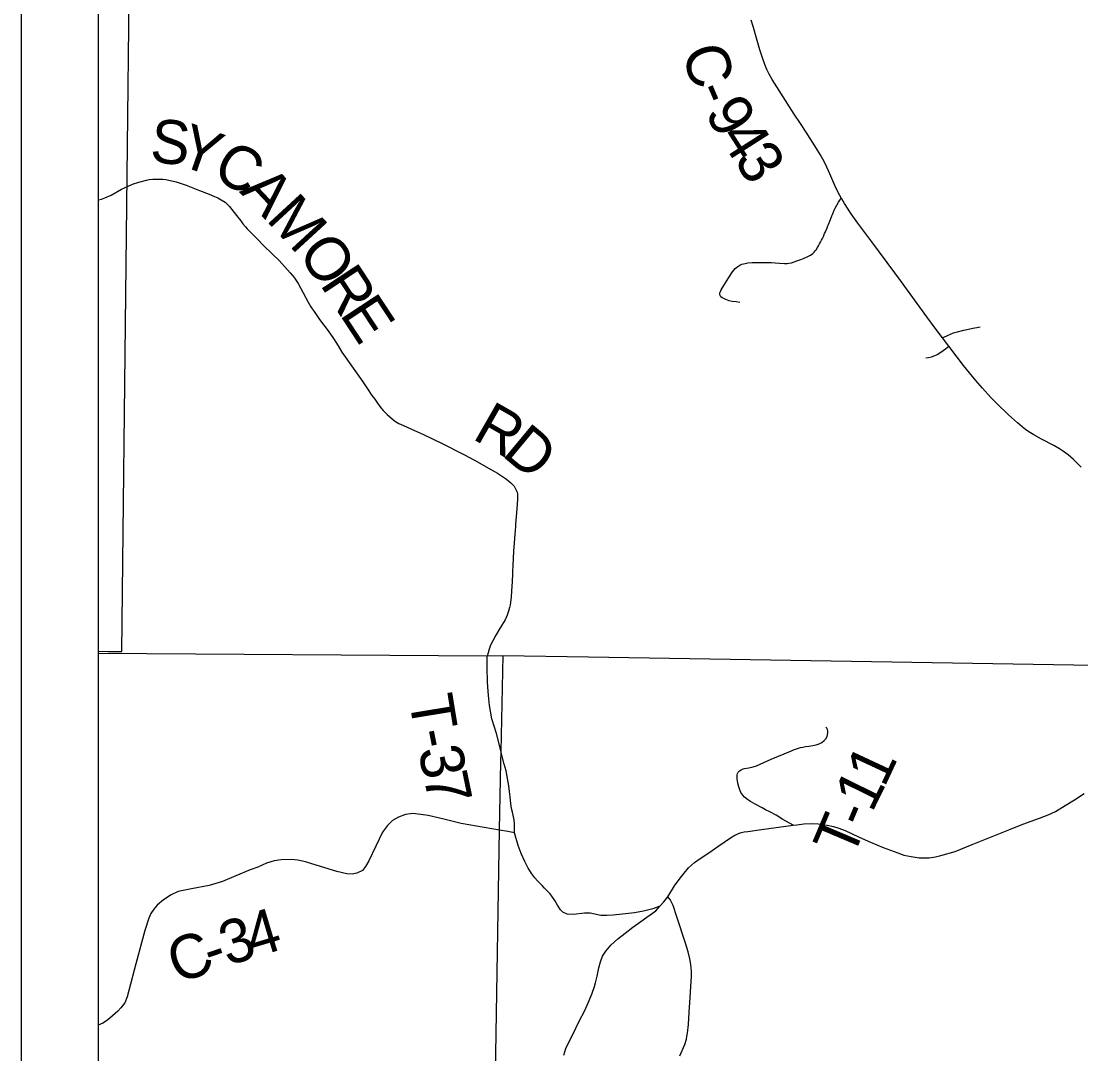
# Model space of a CAD drawing. Extents: x 0 to 34, y 0 to 22.
# Drawn here: x 2 to 3.375, y 18.658 to 19.997 of the extents above; entities that cross this region are included whole.
import ezdxf

# ---------------------------------------------------------------- set-up
doc = ezdxf.new("R2010")
doc.units = 0
for name, color, linetype in [('GM_X_Corporation', 7, 'Continuous'), ('GM_X_County_Road', 7, 'Continuous'), ('GM_X_County_Road_Text', 7, 'Continuous'), ('GM_X_Township_Road', 7, 'Continuous'), ('GM_X_Township_Road_Text', 7, 'Continuous'), ('GM_X_Township_Text', 7, 'Continuous'), ('SH_Data', 7, 'Continuous')]:
    doc.layers.add(name, color=color, linetype=linetype)

msp = doc.modelspace()

# ---------------------------------------------------------------- linework, layer by layer
at = {"layer": 'GM_X_Corporation'}
msp.add_lwpolyline([(2.1, 20.1831), (2.1, 19.1797), (2.1129, 19.1796), (2.1306, 19.1793), (2.142, 20.1827)], close=True, dxfattribs=at)
at = {"layer": 'GM_X_County_Road'}
msp.add_line((3.2036, 19.5753), (3.1953, 19.5861), dxfattribs=at)
for points in [[(3.0642, 19.767), (3.0601, 19.7746), (3.0555, 19.784), (3.049, 19.7988), (3.0433, 19.8113), (3.04, 19.818), (3.0366, 19.824), (3.0317, 19.8319), (3.0183, 19.8529), (3.0109, 19.8643), (3.003, 19.8762), (2.997, 19.8856), (2.9832, 19.9071), (2.9743, 19.9213), (2.9703, 19.9282), (2.9673, 19.9343), (2.9647, 19.9405), (2.9617, 19.9493), (2.9584, 19.9599), (2.954, 19.9749), (2.9499, 19.9886), (2.9469, 19.998)], [(3.1953, 19.5861), (3.1856, 19.5988), (3.1749, 19.6133), (3.1407, 19.6606), (3.1333, 19.6706), (3.1037, 19.7106), (3.0856, 19.7351), (3.0769, 19.7472), (3.068, 19.7606), (3.0645, 19.7664), (3.0642, 19.767)], [(3.3752, 19.4183), (3.3705, 19.4234), (3.3651, 19.4286), (3.3584, 19.4343), (3.3524, 19.4388), (3.3472, 19.4422), (3.3396, 19.4466), (3.3236, 19.455), (3.3138, 19.4603), (3.3075, 19.4642), (3.303, 19.4673), (3.2986, 19.4707), (3.2924, 19.4759), (3.281, 19.4864), (3.2662, 19.5006), (3.258, 19.509), (3.2471, 19.5209), (3.2383, 19.5312), (3.2226, 19.5505), (3.2143, 19.5613), (3.2036, 19.5753)], [(2.8388, 18.8614), (2.8475, 18.8754), (2.8548, 18.8856), (2.86, 18.8918), (2.8659, 18.899), (2.8735, 18.9057), (2.8808, 18.9111), (2.892, 18.9183), (2.9038, 18.9266), (2.9202, 18.9377), (2.9257, 18.9411), (2.9327, 18.9442), (2.938, 18.9456), (2.9426, 18.9462), (2.9603, 18.9487), (3.0016, 18.9541), (3.0061, 18.9546), (3.0153, 18.9558), (3.0248, 18.9563), (3.034, 18.956), (3.0456, 18.9542), (3.0539, 18.9525), (3.0608, 18.9502), (3.0691, 18.9472), (3.0771, 18.9433), (3.0872, 18.9387), (3.1017, 18.9322), (3.1181, 18.9253), (3.1372, 18.9182), (3.1453, 18.9155), (3.1545, 18.9135), (3.1648, 18.912), (3.1782, 18.9119), (3.1861, 18.913), (3.1933, 18.9147), (3.2118, 18.9202), (3.2339, 18.929), (3.2813, 18.9483), (3.2993, 18.9556), (3.321, 18.9632), (3.3325, 18.9677), (3.3417, 18.972), (3.3546, 18.9798), (3.3667, 18.9873), (3.3792, 18.9952)], [(2.6204, 18.9476), (2.5709, 18.9562), (2.5484, 18.9622), (2.5282, 18.9669), (2.5187, 18.9682), (2.5082, 18.9694), (2.4984, 18.9679), (2.4897, 18.9647), (2.4818, 18.9604), (2.4751, 18.9539), (2.4687, 18.9451), (2.4601, 18.9272), (2.4512, 18.9081), (2.4466, 18.9006), (2.4426, 18.8956), (2.4354, 18.8919), (2.4293, 18.8907), (2.4225, 18.8911), (2.4097, 18.8942), (2.3772, 18.9043), (2.3689, 18.9067), (2.3588, 18.9088), (2.3502, 18.9097), (2.3372, 18.9093), (2.3284, 18.9078), (2.3183, 18.905), (2.3069, 18.8999), (2.2972, 18.8964), (2.2786, 18.8884), (2.261, 18.881), (2.244, 18.8758), (2.2208, 18.8716), (2.2038, 18.868), (2.1946, 18.8641), (2.1846, 18.8575), (2.1765, 18.8507), (2.172, 18.8455), (2.1684, 18.8396), (2.1655, 18.8337), (2.1606, 18.8178), (2.1489, 18.7743), (2.1397, 18.7398), (2.1375, 18.7318), (2.1344, 18.7238), (2.1294, 18.7174), (2.1253, 18.7131), (2.1185, 18.7068), (2.112, 18.7015), (2.1061, 18.6976), (2.1, 18.6947)], [(2.8286, 18.8491), (2.8195, 18.8458), (2.8074, 18.8425), (2.7959, 18.8404), (2.7803, 18.8388), (2.7678, 18.8374), (2.7598, 18.837), (2.7519, 18.8372), (2.7383, 18.8401), (2.7308, 18.8402), (2.7164, 18.8385), (2.7083, 18.839), (2.7028, 18.8412), (2.6999, 18.8443), (2.6958, 18.8505), (2.6924, 18.8564), (2.6895, 18.861), (2.6862, 18.8652), (2.679, 18.8726), (2.6757, 18.8758), (2.6697, 18.882), (2.6665, 18.8859), (2.6626, 18.891), (2.6578, 18.8984), (2.6535, 18.907), (2.6487, 18.9175), (2.6448, 18.9277), (2.6402, 18.9443), (2.6315, 18.9459), (2.6204, 18.9476)], [(2.7038, 18.6558), (2.7066, 18.6645), (2.7106, 18.6729), (2.7151, 18.6818), (2.7245, 18.701), (2.7309, 18.713), (2.7342, 18.7206), (2.7402, 18.7352), (2.7437, 18.7449), (2.7453, 18.7497), (2.7474, 18.7586), (2.7496, 18.7691), (2.7515, 18.777), (2.7543, 18.7844), (2.7584, 18.791), (2.765, 18.7986), (2.774, 18.8068), (2.7835, 18.8142), (2.7934, 18.822), (2.8039, 18.8295), (2.8119, 18.8348), (2.8233, 18.8431), (2.8286, 18.8491), (2.8339, 18.8548), (2.8388, 18.8614)]]:
    msp.add_lwpolyline(points, dxfattribs=at)
at = {"layer": 'GM_X_Township_Road'}
for points in [[(2.1, 19.765), (2.1003, 19.7651), (2.1041, 19.7661), (2.1085, 19.7676), (2.1168, 19.7714), (2.1302, 19.7789), (2.138, 19.7826), (2.1443, 19.7855), (2.1527, 19.7883), (2.1626, 19.7907), (2.1662, 19.7914), (2.1709, 19.7919), (2.1795, 19.7921), (2.1836, 19.7919), (2.1876, 19.7914), (2.2009, 19.7887), (2.2139, 19.7842), (2.2312, 19.7775), (2.2439, 19.7725), (2.2507, 19.7696), (2.255, 19.7676), (2.2595, 19.7653), (2.2645, 19.762), (2.268, 19.7589), (2.2703, 19.7566), (2.2794, 19.7449), (2.2848, 19.7378), (2.2876, 19.734), (2.2908, 19.7303), (2.2932, 19.7275), (2.2984, 19.7223), (2.3039, 19.7167), (2.3079, 19.7127), (2.3131, 19.7072), (2.3269, 19.6937), (2.3345, 19.6865), (2.3415, 19.6787), (2.3489, 19.6705), (2.3544, 19.6641), (2.3552, 19.6631), (2.3568, 19.6608), (2.3592, 19.6568), (2.3722, 19.6325), (2.3759, 19.6265), (2.3776, 19.6239), (2.3799, 19.6202), (2.387, 19.61), (2.3981, 19.5955), (2.4052, 19.5852), (2.4112, 19.5758), (2.4162, 19.5678), (2.4202, 19.5618), (2.4307, 19.5467), (2.437, 19.5377), (2.444, 19.5278), (2.4492, 19.5203), (2.4551, 19.5116), (2.4586, 19.5065), (2.4621, 19.5014), (2.4667, 19.4953), (2.4696, 19.4919), (2.4746, 19.4868), (2.4816, 19.4808), (2.4855, 19.4778), (2.4898, 19.4753), (2.4961, 19.4724), (2.5102, 19.466), (2.5221, 19.4608), (2.5461, 19.4493), (2.5741, 19.4348), (2.5882, 19.4276), (2.61, 19.4152), (2.6179, 19.4106), (2.6295, 19.4028), (2.6328, 19.4004), (2.6352, 19.3984), (2.6374, 19.3962), (2.6396, 19.3937), (2.641, 19.3912), (2.6422, 19.3889), (2.6434, 19.386), (2.6439, 19.3837), (2.644, 19.3812), (2.6437, 19.3769), (2.6429, 19.3645), (2.6415, 19.3447), (2.6411, 19.341), (2.6407, 19.3366), (2.6388, 19.3094), (2.6377, 19.2908), (2.6374, 19.2833), (2.6373, 19.2802), (2.6369, 19.2703), (2.6363, 19.2579), (2.6356, 19.2499), (2.6343, 19.24), (2.6336, 19.2364), (2.6323, 19.2316), (2.6303, 19.2264), (2.6277, 19.2207), (2.6213, 19.21), (2.6159, 19.2006), (2.6118, 19.1934), (2.6089, 19.1875), (2.607, 19.1823), (2.6057, 19.1778), (2.6046, 19.1735)], [(2.9324, 19.6322), (2.9275, 19.6329), (2.9225, 19.6335), (2.9187, 19.6344), (2.9141, 19.6359), (2.9116, 19.6371), (2.9095, 19.6381), (2.9079, 19.6395), (2.9072, 19.6402), (2.9068, 19.641), (2.9065, 19.642), (2.9064, 19.6432), (2.9066, 19.6444), (2.9072, 19.6464), (2.9081, 19.6486), (2.9115, 19.6541), (2.9181, 19.6646), (2.9229, 19.6719), (2.9265, 19.676), (2.9297, 19.6788), (2.9322, 19.6803), (2.9351, 19.6817), (2.9373, 19.6824), (2.9392, 19.6828), (2.9429, 19.6833), (2.9482, 19.6838), (2.9534, 19.684), (2.9677, 19.6841), (2.9736, 19.6838), (2.9782, 19.6835), (2.9839, 19.6829), (2.9903, 19.6825), (2.9939, 19.6827), (2.9959, 19.6829), (2.9994, 19.6837), (3.0062, 19.6862), (3.0113, 19.6879), (3.0158, 19.6896), (3.0198, 19.6914), (3.0241, 19.6936), (3.0271, 19.6957), (3.0287, 19.6973), (3.0303, 19.699), (3.0314, 19.7005), (3.0333, 19.7035), (3.0344, 19.7057), (3.0358, 19.7082), (3.0369, 19.7102), (3.0382, 19.7127), (3.0395, 19.7152), (3.0407, 19.7178), (3.0424, 19.7216), (3.0433, 19.7237), (3.0455, 19.7288), (3.0466, 19.7313), (3.0474, 19.7334), (3.0483, 19.7355), (3.0501, 19.7399), (3.0519, 19.7443), (3.0527, 19.7463), (3.0535, 19.7484), (3.0548, 19.7516), (3.0561, 19.7546), (3.0581, 19.7585), (3.0603, 19.7623), (3.0621, 19.7648), (3.0636, 19.7663), (3.0642, 19.767)], [(3.1953, 19.5861), (3.1968, 19.5869), (3.2016, 19.5894), (3.2056, 19.5912), (3.2094, 19.5926), (3.213, 19.5937), (3.2231, 19.5961), (3.2291, 19.5976), (3.2346, 19.5989), (3.2399, 19.5998), (3.2441, 19.6006)], [(3.1736, 19.5602), (3.1773, 19.5607), (3.1809, 19.5615), (3.1845, 19.5628), (3.1883, 19.5648), (3.1931, 19.5678), (3.1992, 19.5721), (3.2036, 19.5753)], [(2.6291, 19.0245), (2.6266, 19.0335), (2.6231, 19.0467), (2.6225, 19.0492), (2.6166, 19.073), (2.6107, 19.0923), (2.6074, 19.1096), (2.6065, 19.1181), (2.6057, 19.1274), (2.6051, 19.1402), (2.6044, 19.1584), (2.6046, 19.1735)], [(3.0016, 18.9541), (2.9883, 18.9618), (2.9794, 18.9671), (2.9713, 18.9714), (2.9658, 18.9743), (2.9615, 18.9766), (2.9521, 18.9814), (2.9461, 18.9848), (2.9422, 18.9874), (2.9386, 18.9904), (2.9363, 18.993), (2.9338, 18.9968), (2.9325, 18.9999), (2.9312, 19.0038), (2.9304, 19.0071), (2.9295, 19.0112), (2.929, 19.0141), (2.9289, 19.0174), (2.929, 19.0194), (2.9293, 19.0214), (2.9304, 19.0231), (2.9321, 19.0249), (2.9341, 19.0262), (2.9366, 19.0273), (2.9386, 19.0277), (2.9441, 19.0286), (2.9497, 19.0297), (2.9539, 19.031), (2.9587, 19.0332), (2.973, 19.0398), (2.9993, 19.0505), (3.0021, 19.0518), (3.0057, 19.0531), (3.0086, 19.0541), (3.0112, 19.0549), (3.0139, 19.0555), (3.0175, 19.0561), (3.022, 19.0567), (3.0269, 19.0575), (3.0312, 19.0585), (3.0352, 19.0599), (3.0387, 19.0615), (3.0419, 19.0639), (3.0439, 19.0661), (3.0456, 19.0692), (3.0463, 19.0714), (3.0467, 19.0742), (3.0466, 19.0763), (3.0462, 19.0784), (3.0453, 19.08), (3.0441, 19.0812)], [(2.6402, 18.9443), (2.6399, 18.9495), (2.6402, 18.9556), (2.6395, 18.9612), (2.6372, 18.9709), (2.6361, 18.9757), (2.6352, 18.9817), (2.6342, 18.9908), (2.6334, 18.9979), (2.6325, 19.0054), (2.6311, 19.0147), (2.6291, 19.0245)], [(2.8547, 18.655), (2.8608, 18.6698), (2.863, 18.6766), (2.8638, 18.6801), (2.8645, 18.6844), (2.8657, 18.6959), (2.8666, 18.7119), (2.8675, 18.7243), (2.8692, 18.7517), (2.8696, 18.7578), (2.8698, 18.765), (2.8689, 18.7737), (2.8675, 18.781), (2.8652, 18.7898), (2.862, 18.8014), (2.8507, 18.8355), (2.8457, 18.8502), (2.8438, 18.8543), (2.8418, 18.8578), (2.8388, 18.8614)]]:
    msp.add_lwpolyline(points, dxfattribs=at)
at = {"layer": 'GM_X_Township_Text'}
msp.add_line((2.1, 19.1775), (2.1, 16.4804), dxfattribs=at)
for points in [[(2.1, 19.1775), (2.6044, 19.174), (2.6249, 19.1744), (2.7359, 19.1727), (3.4968, 19.1598), (3.523, 19.1623), (4.1413, 19.1495), (4.1773, 19.1491), (4.6334, 19.1433), (5.5591, 19.1275), (6.3618, 19.1099), (6.6786, 19.1086), (6.7436, 19.1061), (6.828, 19.1033), (6.8907, 19.103), (7.1115, 19.0999), (7.1957, 19.0991), (7.1974, 19.2018), (7.1981, 19.2461), (7.1982, 19.2496), (7.2244, 20.2649), (7.231, 20.9)], [(7.231, 20.9), (2.1, 20.9), (2.1, 19.1775)], [(2.6249, 19.1744), (2.6223, 19.0497), (2.622, 19.0358), (2.6202, 18.9481), (2.604, 17.9706), (2.6039, 17.9669), (2.5791, 16.4754), (2.4938, 16.4762), (2.1, 16.4804), (2.1, 14.1), (7.1227, 14.1)]]:
    msp.add_lwpolyline(points, dxfattribs=at)
at = {"layer": 'SH_Data'}
for p, q in [((2, 21), (2, 14)), ((2.1, 20.9), (2.1, 14.1))]:
    msp.add_line(p, q, dxfattribs=at)

# ---------------------------------------------------------------- texts
at = {"layer": 'GM_X_County_Road_Text'}
for s, rotation, p in [('C', 287.1512, (2.8565, 19.9578)), ('-', 293.2812, (2.8726, 19.907)), ('9', 301.3657, (2.8858, 19.8778)), ('4', 302.5294, (2.9047, 19.8468)), ('3', 302.7752, (2.9237, 19.8171)), ('3', 17.8458, (2.268, 18.7713)), ('4', 16.7167, (2.301, 18.7819)), ('C', 20.2038, (2.2027, 18.7478)), ('-', 19.02, (2.2462, 18.7638))]:
    msp.add_text(s, height=0.0568, rotation=rotation, dxfattribs=at).set_placement(p)
at = {"layer": 'GM_X_Township_Road_Text'}
for s, rotation, p in [('S', 354.9045, (2.1661, 19.8142)), ('Y', 340.7875, (2.2007, 19.8116)), ('C', 329.9332, (2.2454, 19.7963)), ('A', 313.2662, (2.2823, 19.7756)), ('M', 312.6268, (2.3165, 19.7393)), ('O', 306.8378, (2.3573, 19.6951)), ('R', 303.3675, (2.3867, 19.6558)), ('E', 303.3406, (2.4124, 19.6169)), ('R', 330.2653, (2.5837, 19.4561)), ('D', 320.2672, (2.6221, 19.4344)), ('T', 279.3424, (2.5028, 19.1191)), ('-', 281.3915, (2.5101, 19.0751)), ('3', 281.6535, (2.5147, 19.0521)), ('1', 65.0078, (3.1197, 19.0019)), ('7', 281.757, (2.5217, 19.018)), ('1', 63.7584, (3.1036, 18.9692)), ('T', 67.0788, (3.0783, 18.9094)), ('-', 67.0433, (3.0949, 18.9485))]:
    msp.add_text(s, height=0.0568, rotation=rotation, dxfattribs=at).set_placement(p)

doc.saveas('drawing.dxf')
